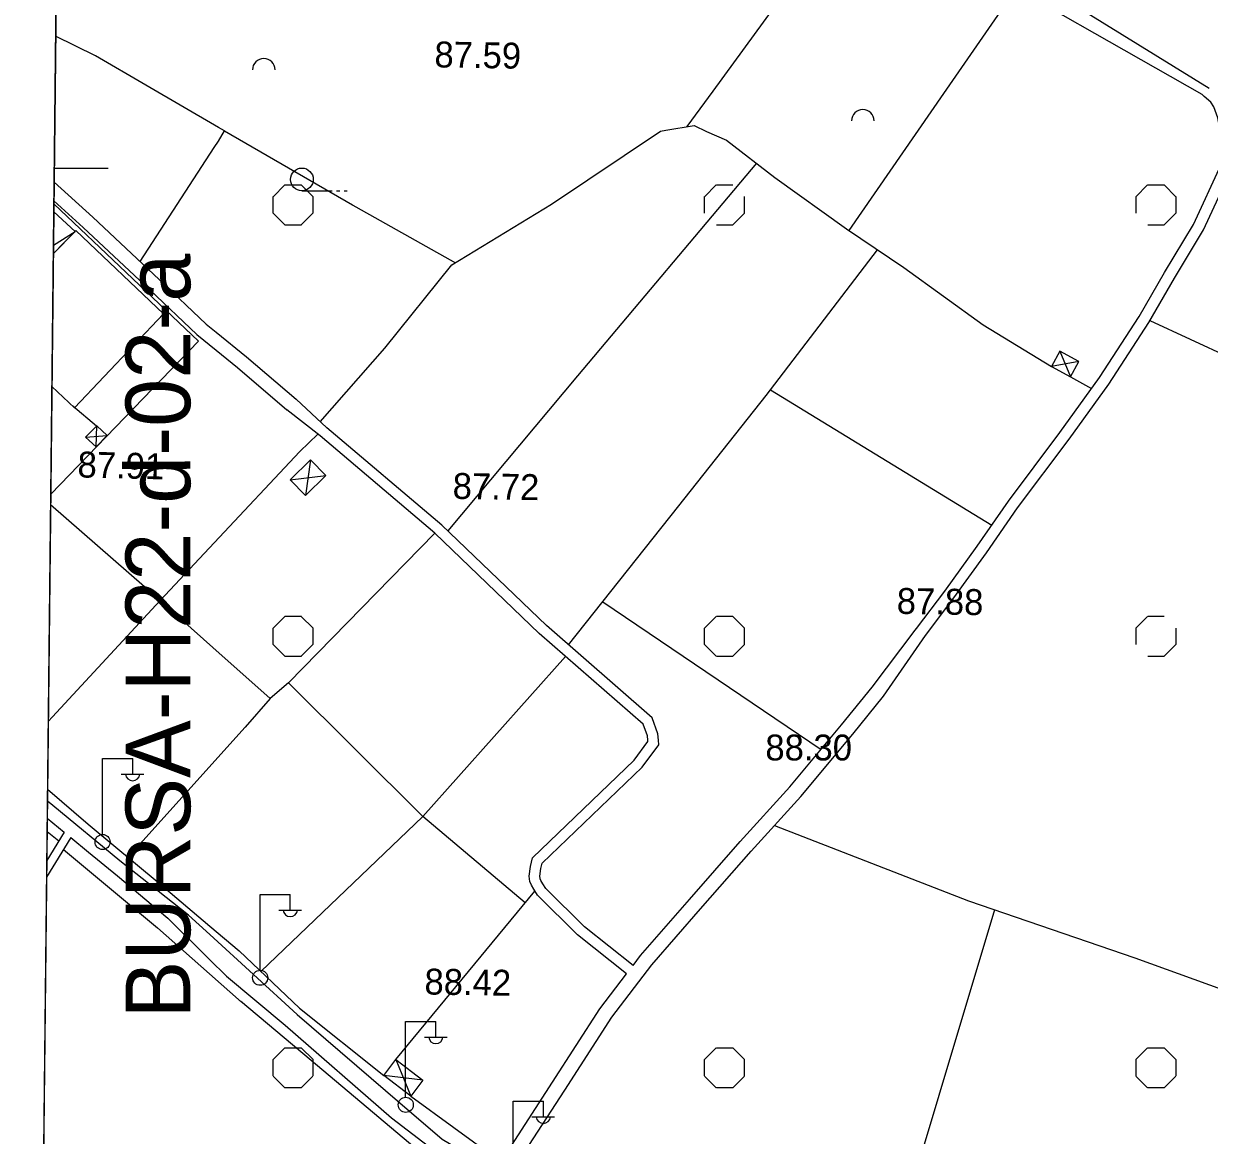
# Model space of a CAD drawing. Extents: x 417995 to 421451, y 4454518 to 4458015.
# Drawn here: x 419147.2 to 419422, y 4456275.9 to 4456533.5 of the extents above; entities that cross this region are included whole.
import ezdxf

# ---------------------------------------------------------------- set-up
doc = ezdxf.new("R2010")
doc.units = 0
for name, color, linetype in [('B_Imalat', 7, 'Continuous'), ('B_Sundurma', 7, 'Continuous'), ('P_Grid', 7, 'Continuous'), ('PAFTALAMA', 7, 'Continuous'), ('PL_KA_TARIM_ALANI', 7, 'Continuous'), ('S_Elektrik_Diregi', 7, 'Continuous'), ('S_Meyvalik', 7, 'Continuous'), ('S_Tek_Agac', 7, 'Continuous'), ('Sinir_Duvar_tek_tarafa_ait', 7, 'Continuous'), ('Sinir_itirazli_Mulkiyet', 7, 'Continuous'), ('Sinir_Tel_bir_taraf', 7, 'Continuous'), ('TR_TARIMALANI', 7, 'Continuous'), ('Y_Kot_Noktasi', 7, 'Continuous'), ('Y_Lejant', 7, 'Continuous'), ('Y_Yol_Kotu', 7, 'Continuous'), ('Yol_Sose', 7, 'Continuous'), ('Yol_Toprak_Duz', 7, 'Continuous'), ('Yol_Toprak_Kesik', 7, 'Continuous')]:
    doc.layers.add(name, color=color, linetype=linetype)

msp = doc.modelspace()

# ---------------------------------------------------------------- linework, layer by layer
at = {"layer": 'B_Imalat'}
msp.add_lwpolyline([(419153.73, 4456449.43), (419158.94, 4456444.49), (419179.61, 4456466.23), (419159.29, 4456485.53), (419154.06, 4456480.14)], dxfattribs=at)
at = {"layer": 'B_Sundurma'}
for p, q in [((419154.08, 4456482.2), (419159.1, 4456485.34)), ((419387.39, 4456457.6), (419389.81, 4456451.67)), ((419391.76, 4456455.19), (419385.45, 4456454.08)), ((419164.03, 4456435.41), (419164.19, 4456440.26)), ((419161.56, 4456437.66), (419166.57, 4456438.03)), ((419213.64, 4456432.41), (419212.51, 4456424.18)), ((419208.95, 4456427.78), (419217.2, 4456428.81)), ((419233.46, 4456293.4), (419236.91, 4456284.92)), ((419239.73, 4456288.6), (419230.64, 4456289.73))]:
    msp.add_line(p, q, dxfattribs=at)
msp.add_lwpolyline([(419154.17, 4456489.92), (419159.1, 4456485.34), (419154.06, 4456480.14)], dxfattribs=at)
for points in [[(419391.76, 4456455.19), (419387.39, 4456457.6), (419385.45, 4456454.08), (419389.81, 4456451.67)], [(419164.03, 4456435.41), (419161.56, 4456437.66), (419164.19, 4456440.26), (419166.57, 4456438.03)], [(419208.95, 4456427.78), (419213.64, 4456432.41), (419217.2, 4456428.81), (419212.51, 4456424.18)], [(419233.46, 4456293.4), (419239.73, 4456288.6), (419236.91, 4456284.92), (419230.64, 4456289.73)]]:
    msp.add_lwpolyline(points, close=True, dxfattribs=at)
at = {"layer": 'P_Grid'}
msp.add_line((419154.27, 4456500), (419166.77, 4456500), dxfattribs=at)
at = {"layer": 'PAFTALAMA'}
for p, q in [((419168.18, 4457798.01), (419138.44, 4455021.89)), ((419154.27, 4456500), (419166.77, 4456500))]:
    msp.add_line(p, q, dxfattribs=at)
at = {"layer": 'PL_KA_TARIM_ALANI'}
msp.add_line((419159.16, 4456956.55), (419138.44, 4455021.89), dxfattribs=at)
at = {"layer": 'S_Elektrik_Diregi'}
for p, q in [((419165.46, 4456345.67), (419165.46, 4456363.17)), ((419165.46, 4456363.17), (419172.46, 4456363.17)), ((419172.46, 4456359.67), (419172.46, 4456363.17)), ((419169.8, 4456359.53), (419175.05, 4456359.53)), ((419201.99, 4456314.19), (419201.99, 4456331.69)), ((419201.99, 4456331.69), (419208.99, 4456331.69)), ((419208.99, 4456328.19), (419208.99, 4456331.69)), ((419206.33, 4456328.05), (419211.58, 4456328.05)), ((419235.73, 4456284.76), (419235.73, 4456302.26)), ((419235.73, 4456302.26), (419242.73, 4456302.26)), ((419242.73, 4456298.76), (419242.73, 4456302.26)), ((419240.07, 4456298.62), (419245.32, 4456298.62)), ((419260.65, 4456266.26), (419260.65, 4456283.76)), ((419260.65, 4456283.76), (419267.65, 4456283.76)), ((419267.65, 4456280.26), (419267.65, 4456283.76)), ((419264.99, 4456280.12), (419270.24, 4456280.12))]:
    msp.add_line(p, q, dxfattribs=at)
for centre in [(419165.49, 4456343.83), (419202.02, 4456312.36), (419235.76, 4456282.92)]:
    msp.add_circle(centre, 1.75, dxfattribs=at)
for centre in [(419172.46, 4456359.68), (419208.99, 4456328.2), (419242.73, 4456298.77), (419267.65, 4456280.28)]:
    msp.add_arc(centre, 1.66, 184.8384, 355.1464, dxfattribs=at)
at = {"layer": 'S_Meyvalik'}
for centre in [(419202.84, 4456522.8), (419341.72, 4456510.98)]:
    msp.add_arc(centre, 2.62, 360, 180, dxfattribs=at)
at = {"layer": 'S_Tek_Agac'}
for p, q in [((419211.69, 4456494.79), (419218.69, 4456494.79)), ((419219.74, 4456494.79), (419220.44, 4456494.79)), ((419221.49, 4456494.79), (419222.19, 4456494.79))]:
    msp.add_line(p, q, dxfattribs=at)
msp.add_circle((419211.69, 4456497.41), 2.63, dxfattribs=at)
at = {"layer": 'Sinir_Duvar_tek_tarafa_ait'}
msp.add_lwpolyline([(419154.19, 4456491.78), (419187.73, 4456459.91), (419153.47, 4456424.48)], dxfattribs=at)
at = {"layer": 'Sinir_itirazli_Mulkiyet'}
for points in [[(419307.01, 4456517.86), (419321.36, 4456537.57)], [(419360.47, 4456517.29), (419375.07, 4456538.44)], [(419163.86, 4456526.02), (419154.6, 4456530.58)], [(419175.48, 4456519.27), (419163.86, 4456526.02)], [(419192.35, 4456509.46), (419175.48, 4456519.27)], [(419301.02, 4456509.65), (419307.01, 4456517.86)], [(419338.54, 4456485.54), (419360.47, 4456517.29)], [(419321.24, 4456347.68), (419366.18, 4456330.2), (419404.71, 4456316.99), (419435.75, 4456305.79), (419462.17, 4456295.91), (419480.05, 4456338.51), (419511.32, 4456413.78), (419542.11, 4456402.26), (419582.61, 4456386.59), (419592.6, 4456382.64), (419605.89, 4456408.74), (419621.01, 4456441.18), (419558.2, 4456464.29), (419515.63, 4456482.76), (419481.23, 4456498.71), (419447.26, 4456516.37)], [(419192.32, 4456506.31), (419193.77, 4456508.64), (419192.36, 4456509.46)], [(419192.36, 4456509.46), (419192.35, 4456509.46)], [(419193.77, 4456508.64), (419223.41, 4456491.48)], [(419215.94, 4456441.25), (419230.89, 4456458.32), (419246.46, 4456477.58), (419269.55, 4456491.66), (419294.8, 4456508.56), (419296.04, 4456508.86), (419302.58, 4456509.89), (419305.47, 4456508.5), (419310.08, 4456506.48), (419321.32, 4456497.89), (419337.9, 4456485.97), (419351.18, 4456476.97), (419369.57, 4456463.68), (419385.45, 4456454.08)], [(419174.16, 4456478.39), (419191.38, 4456504.79), (419192.32, 4456506.31)], [(419192.32, 4456506.31), (419192.32, 4456506.31)], [(419317.06, 4456501.14), (419275.56, 4456451.88), (419245.49, 4456415.94)], [(419222.97, 4456491.73), (419247.28, 4456478.08)], [(419273.48, 4456389.51), (419299.06, 4456421.77), (419319.29, 4456447.3), (419345.12, 4456481.08)], [(419408.23, 4456464.67), (419473.69, 4456434.44), (419512.43, 4456417.23), (419511.32, 4456413.78)], [(419389.81, 4456451.67), (419394.72, 4456448.92)], [(419320.31, 4456448.62), (419371.59, 4456417.24)], [(419211.17, 4456434.36), (419215.34, 4456438.39)], [(419191.33, 4456413.19), (419211.17, 4456434.36)], [(419152.9, 4456371.77), (419178.8, 4456399.84), (419153.44, 4456421.98)], [(419208.59, 4456380.73), (419242.5, 4456415.42)], [(419178.8, 4456399.84), (419191.32, 4456413.19)], [(419191.32, 4456413.19), (419191.33, 4456413.19)], [(419178.8, 4456399.84), (419191.06, 4456388.89)], [(419281.42, 4456399.53), (419332.05, 4456365.29)], [(419191.06, 4456388.89), (419191.07, 4456388.89)], [(419191.07, 4456388.89), (419204.3, 4456377.07), (419198.53, 4456370.47)], [(419263.41, 4456329.72), (419239.75, 4456349.71), (419272.82, 4456386.84)], [(419239.75, 4456349.71), (419208.59, 4456380.73), (419204.3, 4456377.07)], [(419190.78, 4456361.84), (419198.53, 4456370.47)], [(419171.42, 4456340.29), (419190.77, 4456361.84)], [(419190.77, 4456361.84), (419190.78, 4456361.84)], [(419152.73, 4456356.1), (419162.16, 4456347.97), (419178.63, 4456334.31), (419190.37, 4456324.35)], [(419202.17, 4456313.82), (419239.75, 4456349.71)], [(419155.32, 4456344.06), (419152.63, 4456346.15)], [(419156.46, 4456342.12), (419178.25, 4456323.95), (419190.25, 4456313.28)], [(419233.46, 4456293.4), (419265.67, 4456332.47)], [(419372.23, 4456328.13), (419346.39, 4456242.01)], [(419190.37, 4456324.35), (419190.37, 4456324.34)], [(419190.37, 4456324.34), (419197.11, 4456318.63), (419211.15, 4456305.28)], [(419190.25, 4456313.28), (419190.26, 4456313.28)], [(419190.26, 4456313.28), (419197.68, 4456306.68)], [(419218.76, 4456072.45), (419215.23, 4456097.6), (419212.91, 4456114.63), (419212.56, 4456142.64), (419215.82, 4456160.71), (419220.1, 4456181.95), (419228.25, 4456205.56), (419237.29, 4456227.2), (419246.71, 4456249.06), (419249.07, 4456258.19), (419248.99, 4456259.75), (419248.69, 4456261.27), (419248.23, 4456262.68), (419247.24, 4456265.07), (419245.17, 4456266.78), (419213.86, 4456293.21), (419197.42, 4456306.91)], [(419211.15, 4456305.28), (419230.64, 4456289.73)], [(419236.91, 4456284.92), (419256.85, 4456270.43)]]:
    msp.add_lwpolyline(points, dxfattribs=at)
at = {"layer": 'Sinir_Tel_bir_taraf'}
msp.add_lwpolyline([(419164.11, 4456440.19), (419158.59, 4456444.83)], dxfattribs=at)
at = {"layer": 'TR_TARIMALANI'}
for p, q in [((419205.01, 4456493.41), (419207.71, 4456496.12)), ((419207.75, 4456496.14), (419211.58, 4456496.14)), ((419214.26, 4456493.41), (419211.55, 4456496.12)), ((419305.01, 4456493.41), (419307.71, 4456496.12)), ((419307.75, 4456496.14), (419311.58, 4456496.14)), ((419405, 4456493.41), (419407.71, 4456496.12)), ((419407.75, 4456496.14), (419411.58, 4456496.14)), ((419414.25, 4456493.41), (419411.55, 4456496.12)), ((419205.04, 4456489.6), (419205.04, 4456493.43)), ((419214.29, 4456489.6), (419214.29, 4456493.43)), ((419305.04, 4456489.6), (419305.04, 4456493.43)), ((419314.29, 4456489.6), (419314.29, 4456493.43)), ((419405.04, 4456489.6), (419405.04, 4456493.43)), ((419414.29, 4456489.6), (419414.29, 4456493.43)), ((419207.72, 4456486.87), (419205.01, 4456489.58)), ((419211.55, 4456486.87), (419214.25, 4456489.58)), ((419311.55, 4456486.87), (419314.25, 4456489.58)), ((419411.54, 4456486.87), (419414.25, 4456489.58)), ((419207.75, 4456486.89), (419211.58, 4456486.89)), ((419307.75, 4456486.89), (419311.58, 4456486.89)), ((419407.75, 4456486.89), (419411.58, 4456486.89)), ((419205.01, 4456393.41), (419207.71, 4456396.12)), ((419207.75, 4456396.14), (419211.58, 4456396.14)), ((419214.26, 4456393.41), (419211.55, 4456396.12)), ((419305.01, 4456393.41), (419307.71, 4456396.12)), ((419307.75, 4456396.14), (419311.58, 4456396.14)), ((419314.26, 4456393.41), (419311.55, 4456396.12)), ((419405, 4456393.41), (419407.71, 4456396.12)), ((419407.75, 4456396.14), (419411.58, 4456396.14)), ((419205.04, 4456389.6), (419205.04, 4456393.43)), ((419214.29, 4456389.6), (419214.29, 4456393.43)), ((419305.04, 4456389.6), (419305.04, 4456393.43)), ((419314.29, 4456389.6), (419314.29, 4456393.43)), ((419405.04, 4456389.6), (419405.04, 4456393.43)), ((419414.29, 4456389.6), (419414.29, 4456393.43)), ((419207.72, 4456386.87), (419205.01, 4456389.58)), ((419211.55, 4456386.87), (419214.25, 4456389.58)), ((419307.72, 4456386.87), (419305.01, 4456389.58)), ((419311.55, 4456386.87), (419314.25, 4456389.58)), ((419411.54, 4456386.87), (419414.25, 4456389.58)), ((419207.75, 4456386.89), (419211.58, 4456386.89)), ((419307.75, 4456386.89), (419311.58, 4456386.89)), ((419407.75, 4456386.89), (419411.58, 4456386.89)), ((419205.01, 4456293.41), (419207.71, 4456296.12)), ((419207.75, 4456296.14), (419211.58, 4456296.14)), ((419214.26, 4456293.41), (419211.55, 4456296.12)), ((419305.01, 4456293.41), (419307.71, 4456296.12)), ((419307.75, 4456296.14), (419311.58, 4456296.14)), ((419314.26, 4456293.41), (419311.55, 4456296.12)), ((419405, 4456293.41), (419407.71, 4456296.12)), ((419407.75, 4456296.14), (419411.58, 4456296.14)), ((419414.25, 4456293.41), (419411.55, 4456296.12)), ((419205.04, 4456289.6), (419205.04, 4456293.43)), ((419214.29, 4456289.6), (419214.29, 4456293.43)), ((419305.04, 4456289.6), (419305.04, 4456293.43)), ((419314.29, 4456289.6), (419314.29, 4456293.43)), ((419405.04, 4456289.6), (419405.04, 4456293.43)), ((419414.29, 4456289.6), (419414.29, 4456293.43)), ((419207.72, 4456286.87), (419205.01, 4456289.58)), ((419211.55, 4456286.87), (419214.25, 4456289.58)), ((419307.72, 4456286.87), (419305.01, 4456289.58)), ((419311.55, 4456286.87), (419314.25, 4456289.58)), ((419407.71, 4456286.87), (419405.01, 4456289.58)), ((419411.54, 4456286.87), (419414.25, 4456289.58)), ((419207.75, 4456286.89), (419211.58, 4456286.89)), ((419307.75, 4456286.89), (419311.58, 4456286.89)), ((419407.75, 4456286.89), (419411.58, 4456286.89))]:
    msp.add_line(p, q, dxfattribs=at)
at = {"layer": 'Y_Lejant'}
msp.add_lwpolyline([(419168.18, 4457798.01), (421295.36, 4457775.52), (421266.41, 4454999.4), (419138.44, 4455021.89)], close=True, dxfattribs=at)
at = {"layer": 'Yol_Sose'}
for points in [[(419190.35, 4456322.37), (419185.43, 4456326.88), (419169.52, 4456339.44), (419153.97, 4456352.3), (419152.7, 4456353.3)], [(419152.66, 4456349.33), (419156.57, 4456346.11)], [(419158.12, 4456344.84), (419162.19, 4456341.5), (419168.96, 4456335.99), (419180.6, 4456326.19), (419190.29, 4456316.61)], [(419190.35, 4456322.36), (419190.35, 4456322.37)], [(419210.6, 4456303.81), (419190.35, 4456322.36)], [(419190.29, 4456316.61), (419190.29, 4456316.61)], [(419190.29, 4456316.61), (419194.23, 4456312.72), (419207.78, 4456301.38)], [(419210.6, 4456303.81), (419234.38, 4456283.37), (419244.21, 4456274.92), (419251.56, 4456270.64), (419253.88, 4456269.98), (419254.14, 4456269.95), (419255.09, 4456269.99), (419256.42, 4456270.35)], [(419207.78, 4456301.38), (419232.48, 4456279.93), (419248.26, 4456267.8), (419250.44, 4456265.57), (419251.57, 4456263.85), (419252.3, 4456262.09), (419252.54, 4456260.46), (419250.31, 4456252.45)]]:
    msp.add_lwpolyline(points, dxfattribs=at)
at = {"layer": 'Yol_Toprak_Duz'}
for points in [[(419362.56, 4456550.73), (419362.64, 4456550.49), (419363.16, 4456549.66), (419420.31, 4456517.14)], [(419420.85, 4456516.65), (419420.31, 4456517.14)], [(419424.72, 4456500.83), (419424.72, 4456500.86), (419425.04, 4456505.79), (419423.98, 4456511.67), (419423.07, 4456514.2), (419422.36, 4456515.29), (419420.85, 4456516.65)], [(419356.21, 4456391.72), (419362.79, 4456400.43), (419370.4, 4456410.86), (419377.58, 4456421.31), (419389.51, 4456437.21), (419398.74, 4456449.98), (419407.98, 4456464.23), (419413.92, 4456474.51), (419420.7, 4456485.71), (419427.12, 4456499.73)], [(419154.19, 4456492.42), (419160.97, 4456486.23), (419176.4, 4456471.84), (419187.35, 4456461.44), (419191.8, 4456457.81)], [(419191.8, 4456457.81), (419191.8, 4456457.81)], [(419191.8, 4456457.81), (419196.75, 4456453.79), (419208.2, 4456444.02)], [(419215.91, 4456437.94), (419208.2, 4456444.02)], [(419291.87, 4456367.44), (419291.81, 4456368.4), (419290.77, 4456371.17), (419266.7, 4456392.19), (419242.5, 4456415.42), (419215.91, 4456437.94)], [(419262.31, 4456270.42), (419272.61, 4456286.34), (419283.51, 4456303.2), (419292.78, 4456315.39), (419304.04, 4456328.31), (419315.79, 4456341.67), (419327.34, 4456354.4), (419339.38, 4456368.83), (419346.49, 4456377.63), (419356.21, 4456391.72)], [(419266.92, 4456335.33), (419266.89, 4456335.39), (419266.81, 4456335.91), (419267.09, 4456337.69), (419267.37, 4456338.89), (419290.53, 4456361.15), (419294.4, 4456366.36), (419294.32, 4456367.44)], [(419158.12, 4456344.84), (419152.51, 4456335.66)], [(419286.95, 4456313.27), (419275.53, 4456322.32), (419266.31, 4456331.5), (419265.41, 4456332.86), (419264.89, 4456333.84), (419264.53, 4456334.71), (419264.42, 4456335.33)]]:
    msp.add_lwpolyline(points, dxfattribs=at)
at = {"layer": 'Yol_Toprak_Kesik'}
for points in [[(419368.66, 4456551.73), (419368.76, 4456551.47), (419422, 4456518.53)], [(419354.11, 4456393.31), (419360.68, 4456402), (419368.24, 4456412.38), (419375.44, 4456422.85), (419387.39, 4456438.77), (419396.56, 4456451.47), (419405.73, 4456465.6), (419411.65, 4456475.85), (419418.36, 4456486.94), (419424.72, 4456500.83)], [(419154.24, 4456496.79), (419163.19, 4456488.63), (419178.63, 4456474.22), (419189.5, 4456463.89), (419191.85, 4456461.98)], [(419191.85, 4456461.98), (419191.85, 4456461.98)], [(419191.85, 4456461.98), (419198.84, 4456456.29), (419210.32, 4456446.5)], [(419210.32, 4456446.5), (419217.49, 4456439.81)], [(419294.32, 4456367.44), (419294.22, 4456368.92), (419292.85, 4456372.6), (419268.35, 4456393.99), (419244.14, 4456417.24), (419217.49, 4456439.81)], [(419288.43, 4456315.22), (419290.17, 4456317.51), (419301.51, 4456330.53), (419313.28, 4456343.92), (419324.8, 4456356.61), (419336.79, 4456370.96), (419343.84, 4456379.7), (419353.83, 4456392.92), (419354.11, 4456393.31)], [(419264.42, 4456335.33), (419264.33, 4456335.9), (419264.69, 4456338.16), (419265.15, 4456340.16), (419288.69, 4456362.78), (419291.89, 4456367.1), (419291.87, 4456367.44)], [(419156.57, 4456346.11), (419152.56, 4456339.54)], [(419288.43, 4456315.22), (419277.16, 4456324.16), (419268.21, 4456333.05), (419267.52, 4456334.11), (419267.1, 4456334.89), (419266.92, 4456335.33)], [(419259.49, 4456272.25), (419269.79, 4456288.17), (419280.76, 4456305.14), (419286.95, 4456313.27)]]:
    msp.add_lwpolyline(points, dxfattribs=at)

# ---------------------------------------------------------------- texts
at = {"layer": 'PAFTALAMA'}
msp.add_text('BURSA-H22-d-02-a', height=15, rotation=90, dxfattribs=at).set_placement((419185.81, 4456302.95))
at = {"layer": 'Y_Kot_Noktasi'}
for s, rotation, p in [('87.59', 359.0723, (419242.37, 4456523.39)), ('87.91', 358.6331, (419159.63, 4456428.35)), ('87.72', 359.0723, (419246.59, 4456423.38)), ('87.88', 359.0723, (419349.52, 4456396.73)), ('88.42', 359.0723, (419240.06, 4456308.5))]:
    msp.add_text(s, height=6, rotation=rotation, dxfattribs=at).set_placement(p)
at = {"layer": 'Y_Yol_Kotu'}
msp.add_text('88.30', height=6, dxfattribs=at).set_placement((419319.11, 4456362.73))

doc.saveas('drawing.dxf')
